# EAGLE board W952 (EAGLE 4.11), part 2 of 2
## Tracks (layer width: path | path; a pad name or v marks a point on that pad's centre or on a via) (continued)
N$696 (continued)
  Bottom 0.508: SV62.12 136.53,74.3 140.34,70.49 IC31.24 IC39.24
N$699
  Bottom 0.508: SV63.2 95.25,48.9 99.06,52.71 IC32.1 IC40.1
N$700
  Bottom 0.508: SV63.3 98.42,49.53 101.6,52.71 IC32.2 IC40.2
N$701
  Bottom 0.508: SV63.4 101.6,48.9 104.14,51.44 IC32.3 IC40.3
N$702
  Bottom 0.508: SV63.5 104.78,48.9 106.68,50.8 IC32.4 IC40.4
N$703
  Bottom 0.508: SV63.6 107.95,48.9 109.22,50.17 IC32.5 IC40.5
N$704
  Bottom 0.508: SV63.7 111.76,48.26 IC32.6 IC40.6
N$705
  Bottom 0.508: SV63.8 IC32.7 IC40.7
N$706
  Bottom 0.508: SV63.9 116.84,48.26 IC32.8 IC40.8
N$707
  Bottom 0.508: SV63.10 120.65,48.9 119.38,50.17 IC32.9 IC40.9
N$708
  Bottom 0.508: SV63.11 123.83,48.9 121.92,50.8 IC32.10 IC40.10
N$709
  Bottom 0.508: SV63.12 127,48.9 124.46,51.44 IC32.11 IC40.11
N$710
  Bottom 0.508: SV63.13 130.18,49.53 127,52.71 IC32.12 IC40.12
N$711
  Bottom 0.508: SV64.1 130.18,74.93 127,71.76 IC32.13 IC40.13
N$712
  Bottom 0.508: SV64.2 127,74.93 124.46,72.39 IC32.14 IC40.14
N$713
  Bottom 0.508: SV64.3 123.83,74.93 121.92,73.03 IC32.15 IC40.15
N$714
  Bottom 0.508: SV64.4 120.65,74.93 119.38,73.66 IC32.16 IC40.16
N$715
  Bottom 0.508: SV64.5 116.84,75.57 IC32.17 IC40.17
N$716
  Bottom 0.508: SV64.6 IC32.18 IC40.18
N$717
  Bottom 0.508: SV64.7 111.76,75.57 IC32.19 IC40.19
N$718
  Bottom 0.508: SV64.8 107.95,74.93 109.22,73.66 IC32.20 IC40.20
N$719
  Bottom 0.508: SV64.9 104.78,74.93 106.68,73.03 IC32.21 IC40.21
N$720
  Bottom 0.508: SV64.10 101.6,74.93 104.14,72.39 IC32.22 IC40.22
N$721
  Bottom 0.508: SV64.11 98.42,74.93 101.6,71.76 IC32.23 IC40.23
N$722
  Bottom 0.508: SV64.12 95.25,74.3 99.06,70.49 IC32.24 IC40.24
N$725
  Bottom 0.508: SV65.2 136.53,87 140.34,90.81 IC33.1 IC41.1
N$726
  Bottom 0.508: SV65.3 139.7,87.63 142.88,90.81 IC33.2 IC41.2
N$727
  Bottom 0.508: SV65.4 142.88,87 145.41,89.54 IC33.3 IC41.3
N$728
  Bottom 0.508: SV65.5 146.05,87 147.96,88.9 IC33.4 IC41.4
N$729
  Bottom 0.508: SV65.6 149.22,87 150.5,88.27 IC33.5 IC41.5
N$730
  Bottom 0.508: SV65.7 153.03,86.36 IC33.6 IC41.6
N$731
  Bottom 0.508: SV65.8 IC33.7 IC41.7
N$732
  Bottom 0.508: SV65.9 158.12,86.36 IC33.8 IC41.8
N$733
  Bottom 0.508: SV65.10 161.93,87 160.66,88.27 IC33.9 IC41.9
N$734
  Bottom 0.508: SV65.11 165.1,87 163.19,88.9 IC33.10 IC41.10
N$735
  Bottom 0.508: SV65.12 168.28,87 165.74,89.54 IC33.11 IC41.11
N$736
  Bottom 0.508: SV65.13 171.45,87.63 168.28,90.81 IC33.12 IC41.12
N$737
  Bottom 0.508: SV66.1 171.45,113.03 168.28,109.86 IC33.13 IC41.13
N$738
  Bottom 0.508: SV66.2 168.28,113.03 165.74,110.49 IC33.14 IC41.14
N$739
  Bottom 0.508: SV66.3 165.1,113.03 163.19,111.13 IC33.15 IC41.15
N$740
  Bottom 0.508: SV66.4 161.93,113.03 160.66,111.76 IC33.16 IC41.16
N$741
  Bottom 0.508: SV66.5 158.12,113.67 IC33.17 IC41.17
N$742
  Bottom 0.508: SV66.6 IC33.18 IC41.18
N$743
  Bottom 0.508: SV66.7 153.03,113.67 IC33.19 IC41.19
N$744
  Bottom 0.508: SV66.8 149.22,113.03 150.5,111.76 IC33.20 IC41.20
N$745
  Bottom 0.508: SV66.9 146.05,113.03 147.96,111.13 IC33.21 IC41.21
N$746
  Bottom 0.508: SV66.10 142.88,113.03 145.41,110.49 IC33.22 IC41.22
N$747
  Bottom 0.508: SV66.11 139.7,113.03 142.88,109.86 IC33.23 IC41.23
N$748
  Bottom 0.508: SV66.12 136.53,112.4 140.34,108.59 IC33.24 IC41.24
N$751
  Bottom 0.508: SV67.2 95.25,87 99.06,90.81 IC34.1 IC42.1
N$752
  Bottom 0.508: SV67.3 98.42,87.63 101.6,90.81 IC34.2 IC42.2
N$753
  Bottom 0.508: SV67.4 101.6,87 104.14,89.54 IC34.3 IC42.3
N$754
  Bottom 0.508: SV67.5 104.78,87 106.68,88.9 IC34.4 IC42.4
N$755
  Bottom 0.508: SV67.6 107.95,87 109.22,88.27 IC34.5 IC42.5
N$756
  Bottom 0.508: SV67.7 111.76,86.36 IC34.6 IC42.6
N$757
  Bottom 0.508: SV67.8 IC34.7 IC42.7
N$758
  Bottom 0.508: SV67.9 116.84,86.36 IC34.8 IC42.8
N$759
  Bottom 0.508: SV67.10 120.65,87 119.38,88.27 IC34.9 IC42.9
N$760
  Bottom 0.508: SV67.11 123.83,87 121.92,88.9 IC34.10 IC42.10
N$761
  Bottom 0.508: SV67.12 127,87 124.46,89.54 IC34.11 IC42.11
N$762
  Bottom 0.508: SV67.13 130.18,87.63 127,90.81 IC34.12 IC42.12
N$763
  Bottom 0.508: SV68.1 130.18,113.03 127,109.86 IC34.13 IC42.13
N$764
  Bottom 0.508: SV68.2 127,113.03 124.46,110.49 IC34.14 IC42.14
N$765
  Bottom 0.508: SV68.3 123.83,113.03 121.92,111.13 IC34.15 IC42.15
N$766
  Bottom 0.508: SV68.4 120.65,113.03 119.38,111.76 IC34.16 IC42.16
N$767
  Bottom 0.508: SV68.5 116.84,113.67 IC34.17 IC42.17
N$768
  Bottom 0.508: SV68.6 IC34.18 IC42.18
N$769
  Bottom 0.508: SV68.7 111.76,113.67 IC34.19 IC42.19
N$770
  Bottom 0.508: SV68.8 107.95,113.03 109.22,111.76 IC34.20 IC42.20
N$771
  Bottom 0.508: SV68.9 104.78,113.03 106.68,111.13 IC34.21 IC42.21
N$772
  Bottom 0.508: SV68.10 101.6,113.03 104.14,110.49 IC34.22 IC42.22
N$773
  Bottom 0.508: SV68.11 98.42,113.03 101.6,109.86 IC34.23 IC42.23
N$774
  Bottom 0.508: SV68.12 95.25,112.4 99.06,108.59 IC34.24 IC42.24
N$777
  Bottom 0.508: SV69.2 136.53,125.1 140.34,128.91 IC35.1 IC43.1
N$778
  Bottom 0.508: SV69.3 139.7,125.73 142.88,128.91 IC35.2 IC43.2
N$779
  Bottom 0.508: SV69.4 142.88,125.1 145.41,127.64 IC35.3 IC43.3
N$780
  Bottom 0.508: SV69.5 146.05,125.1 147.96,127 IC35.4 IC43.4
N$781
  Bottom 0.508: SV69.6 149.22,125.1 150.5,126.37 IC35.5 IC43.5
N$782
  Bottom 0.508: SV69.7 153.03,124.46 IC35.6 IC43.6
N$783
  Bottom 0.508: SV69.8 IC35.7 IC43.7
N$784
  Bottom 0.508: SV69.9 158.12,124.46 IC35.8 IC43.8
N$785
  Bottom 0.508: SV69.10 161.93,125.1 160.66,126.37 IC35.9 IC43.9
N$786
  Bottom 0.508: SV69.11 165.1,125.1 163.19,127 IC35.10 IC43.10
N$787
  Bottom 0.508: SV69.12 168.28,125.1 165.74,127.64 IC35.11 IC43.11
N$788
  Bottom 0.508: SV69.13 171.45,125.73 168.28,128.91 IC35.12 IC43.12
N$789
  Bottom 0.508: SV70.1 171.45,151.13 168.28,147.96 IC35.13 IC43.13
N$790
  Bottom 0.508: SV70.2 168.28,151.13 165.74,148.59 IC35.14 IC43.14
N$791
  Bottom 0.508: SV70.3 165.1,151.13 163.19,149.23 IC35.15 IC43.15
N$792
  Bottom 0.508: SV70.4 161.93,151.13 160.66,149.86 IC35.16 IC43.16
N$793
  Bottom 0.508: SV70.5 158.12,151.77 IC35.17 IC43.17
N$794
  Bottom 0.508: SV70.6 IC35.18 IC43.18
N$795
  Bottom 0.508: SV70.7 153.03,151.77 IC35.19 IC43.19
N$796
  Bottom 0.508: SV70.8 149.22,151.13 150.5,149.86 IC35.20 IC43.20
N$797
  Bottom 0.508: SV70.9 146.05,151.13 147.96,149.23 IC35.21 IC43.21
N$798
  Bottom 0.508: SV70.10 142.88,151.13 145.41,148.59 IC35.22 IC43.22
N$799
  Bottom 0.508: SV70.11 139.7,151.13 142.88,147.96 IC35.23 IC43.23
N$800
  Bottom 0.508: SV70.12 136.53,150.5 140.34,146.69 IC35.24 IC43.24
N$803
  Bottom 0.508: SV71.2 95.25,125.1 99.06,128.91 IC36.1 IC44.1
N$804
  Bottom 0.508: SV71.3 98.42,125.73 101.6,128.91 IC36.2 IC44.2
N$805
  Bottom 0.508: SV71.4 101.6,125.1 104.14,127.64 IC36.3 IC44.3
N$806
  Bottom 0.508: SV71.5 104.78,125.1 106.68,127 IC36.4 IC44.4
N$807
  Bottom 0.508: SV71.6 107.95,125.1 109.22,126.37 IC36.5 IC44.5
N$808
  Bottom 0.508: SV71.7 111.76,124.46 IC36.6 IC44.6
N$809
  Bottom 0.508: SV71.8 IC36.7 IC44.7
N$810
  Bottom 0.508: SV71.9 116.84,124.46 IC36.8 IC44.8
N$811
  Bottom 0.508: SV71.10 120.65,125.1 119.38,126.37 IC36.9 IC44.9
N$812
  Bottom 0.508: SV71.11 123.83,125.1 121.92,127 IC36.10 IC44.10
N$813
  Bottom 0.508: SV71.12 127,125.1 124.46,127.64 IC36.11 IC44.11
N$814
  Bottom 0.508: SV71.13 130.18,125.73 127,128.91 IC36.12 IC44.12
N$815
  Bottom 0.508: SV72.1 130.18,151.13 127,147.96 IC36.13 IC44.13
N$816
  Bottom 0.508: SV72.2 127,151.13 124.46,148.59 IC36.14 IC44.14
N$817
  Bottom 0.508: SV72.3 123.83,151.13 121.92,149.23 IC36.15 IC44.15
N$818
  Bottom 0.508: SV72.4 120.65,151.13 119.38,149.86 IC36.16 IC44.16
N$819
  Bottom 0.508: SV72.5 116.84,151.77 IC36.17 IC44.17
N$820
  Bottom 0.508: SV72.6 IC36.18 IC44.18
N$821
  Bottom 0.508: SV72.7 111.76,151.77 IC36.19 IC44.19
N$822
  Bottom 0.508: SV72.8 107.95,151.13 109.22,149.86 IC36.20 IC44.20
N$823
  Bottom 0.508: SV72.9 104.78,151.13 106.68,149.23 IC36.21 IC44.21
N$824
  Bottom 0.508: SV72.10 101.6,151.13 104.14,148.59 IC36.22 IC44.22
N$825
  Bottom 0.508: SV72.11 98.42,151.13 101.6,147.96 IC36.23 IC44.23
N$826
  Bottom 0.508: SV72.12 95.25,150.5 99.06,146.69 IC36.24 IC44.24
N$829
  Bottom 0.508: SV73.2 136.53,163.2 140.34,167.01 IC37.1 IC45.1
N$830
  Bottom 0.508: SV73.3 139.7,163.83 142.88,167.01 IC37.2 IC45.2
N$831
  Bottom 0.508: SV73.4 142.88,163.2 145.41,165.74 IC37.3 IC45.3
N$832
  Bottom 0.508: SV73.5 146.05,163.2 147.96,165.1 IC37.4 IC45.4
N$833
  Bottom 0.508: SV73.6 149.22,163.2 150.5,164.47 IC37.5 IC45.5
N$834
  Bottom 0.508: SV73.7 153.03,162.56 IC37.6 IC45.6
N$835
  Bottom 0.508: SV73.8 IC37.7 IC45.7
N$836
  Bottom 0.508: SV73.9 158.12,162.56 IC37.8 IC45.8
N$837
  Bottom 0.508: SV73.10 161.93,163.2 160.66,164.47 IC37.9 IC45.9
N$838
  Bottom 0.508: SV73.11 165.1,163.2 163.19,165.1 IC37.10 IC45.10
N$839
  Bottom 0.508: SV73.12 168.28,163.2 165.74,165.74 IC37.11 IC45.11
N$840
  Bottom 0.508: SV73.13 171.45,163.83 168.28,167.01 IC37.12 IC45.12
N$841
  Bottom 0.508: SV74.1 171.45,189.23 168.28,186.06 IC37.13 IC45.13
N$842
  Bottom 0.508: SV74.2 168.28,189.23 165.74,186.69 IC37.14 IC45.14
N$843
  Bottom 0.508: SV74.3 165.1,189.23 163.19,187.33 IC37.15 IC45.15
N$844
  Bottom 0.508: SV74.4 161.93,189.23 160.66,187.96 IC37.16 IC45.16
N$845
  Bottom 0.508: SV74.5 158.12,189.87 IC37.17 IC45.17
N$846
  Bottom 0.508: SV74.6 IC37.18 IC45.18
N$847
  Bottom 0.508: SV74.7 153.03,189.87 IC37.19 IC45.19
N$848
  Bottom 0.508: SV74.8 149.22,189.23 150.5,187.96 IC37.20 IC45.20
N$849
  Bottom 0.508: SV74.9 146.05,189.23 147.96,187.33 IC37.21 IC45.21
N$850
  Bottom 0.508: SV74.10 142.88,189.23 145.41,186.69 IC37.22 IC45.22
N$851
  Bottom 0.508: SV74.11 139.7,189.23 142.88,186.06 IC37.23 IC45.23
N$852
  Bottom 0.508: SV74.12 136.53,188.6 140.34,184.79 IC37.24 IC45.24
N$855
  Bottom 0.508: SV75.2 95.25,163.2 99.06,167.01 IC38.1 IC46.1
N$856
  Bottom 0.508: SV75.3 98.42,163.83 101.6,167.01 IC38.2 IC46.2
N$857
  Bottom 0.508: SV75.4 101.6,163.2 104.14,165.74 IC38.3 IC46.3
N$858
  Bottom 0.508: SV75.5 104.78,163.2 106.68,165.1 IC38.4 IC46.4
N$859
  Bottom 0.508: SV75.6 107.95,163.2 109.22,164.47 IC38.5 IC46.5
N$860
  Bottom 0.508: SV75.7 111.76,162.56 IC38.6 IC46.6
N$861
  Bottom 0.508: SV75.8 IC38.7 IC46.7
N$862
  Bottom 0.508: SV75.9 116.84,162.56 IC38.8 IC46.8
N$863
  Bottom 0.508: SV75.10 120.65,163.2 119.38,164.47 IC38.9 IC46.9
N$864
  Bottom 0.508: SV75.11 123.83,163.2 121.92,165.1 IC38.10 IC46.10
N$865
  Bottom 0.508: SV75.12 127,163.2 124.46,165.74 IC38.11 IC46.11
N$866
  Bottom 0.508: SV75.13 130.18,163.83 127,167.01 IC38.12 IC46.12
N$867
  Bottom 0.508: SV76.1 130.18,189.23 127,186.06 IC38.13 IC46.13
N$868
  Bottom 0.508: SV76.2 127,189.23 124.46,186.69 IC38.14 IC46.14
N$869
  Bottom 0.508: SV76.3 123.83,189.23 121.92,187.33 IC38.15 IC46.15
N$870
  Bottom 0.508: SV76.4 120.65,189.23 119.38,187.96 IC38.16 IC46.16
N$871
  Bottom 0.508: SV76.5 116.84,189.87 IC38.17 IC46.17
N$872
  Bottom 0.508: SV76.6 IC38.18 IC46.18
N$873
  Bottom 0.508: SV76.7 111.76,189.87 IC38.19 IC46.19
N$874
  Bottom 0.508: SV76.8 107.95,189.23 109.22,187.96 IC38.20 IC46.20
N$875
  Bottom 0.508: SV76.9 104.78,189.23 106.68,187.33 IC38.21 IC46.21
N$876
  Bottom 0.508: SV76.10 101.6,189.23 104.14,186.69 IC38.22 IC46.22
N$877
  Bottom 0.508: SV76.11 98.42,189.23 101.6,186.06 IC38.23 IC46.23
N$878
  Bottom 0.508: SV76.12 95.25,188.6 99.06,184.79 IC38.24 IC46.24
VCC
  Bottom 0.762: SV54.9 C27.1 16.51,76.2 | C22.1 SV44.9 33.66,76.2 31.75,74.3 21.59,74.3 19.68,76.2 16.51,76.2 | SV56.9 C28.1 16.51,107.95 | C23.1 SV46.9 33.66,107.95 31.75,106.05 21.59,106.05 19.68,107.95 16.51,107.95 | 16.51,107.95 16.51,76.2 | C16.1 SV32.9 64.14,43.82 64.14,36.83 C40.+ 59.05,30.48 | 59.05,30.48 U$5.A1 57.15,31.75 44.45,44.45 C21.1 SV42.9 33.66,44.45 31.75,42.55 21.59,42.55 19.68,44.45 16.51,44.45 | SV52.9 C26.1 16.51,44.45 | 59.05,30.48 59.05,20.96 58.42,20.32 58.42,13.97 U$1.DA2 | 16.51,76.2 16.51,44.45 | C33.1 SV66.13 130.81,116.84 94.61,116.84 SV68.13 92.08,106.05 | 92.08,106.05 C34.1 | 73.66,107.95 76.83,107.95 78.74,106.05 92.08,106.05 | 73.66,107.95 C18.1 SV36.9 59.69,111.76 59.69,139.07 | SV62.13 C31.1 | SV34.9 C17.1 73.66,76.2 | 92.08,74.3 C32.1 | 92.08,74.3 SV64.13 94.61,78.74 130.81,78.74 SV62.13 | 73.66,76.2 76.83,76.2 78.74,74.3 92.08,74.3 | 73.66,76.2 73.66,107.95 | C37.1 SV74.13 130.81,193.04 94.61,193.04 SV76.13 C38.1 92.08,175.26 90.17,173.36 90.17,168.91 | C35.1 SV70.13 130.81,154.94 90.81,154.94 | C36.1 SV72.13 92.08,153.67 90.81,154.94 | 90.17,168.91 90.17,155.58 90.81,154.94 | C19.1 SV38.9 60.33,139.7 59.69,139.07 | SV58.9 C29.1 16.51,139.7 | 16.51,139.7 19.68,139.7 21.59,137.8 31.75,137.8 33.66,139.7 SV48.9 C24.1 43.18,139.7 45.09,137.8 58.42,137.8 59.69,139.07 | SV60.9 C30.1 16.51,171.45 | 16.51,171.45 19.68,171.45 21.59,169.55 31.75,169.55 33.66,171.45 SV50.9 C25.1 43.18,171.45 45.09,169.55 58.42,169.55 60.33,171.45 SV40.9 64.14,170.82 C20.1 71.75,170.82 73.66,168.91 90.17,168.91 | 16.51,139.7 16.51,171.45 | 16.51,139.7 16.51,107.95 | U$1.CA2 128.27,13.97 128.27,16.51 128.91,17.15 128.91,23.5 127,25.4 U$4.A1 127.64,29.21 130.81,29.21 146.05,44.45 SV22.9 C11.1 185.42,43.82 195.58,33.66
  Bottom 0.762: SV12.9 C6.1 | 195.58,33.66 192.41,30.48 | 192.41,30.48 U$3.A1 | 195.58,33.66 C39.+ SV12.9 | 192.41,30.48 192.41,20.96 191.77,20.32 191.77,13.97 U$1.BA2 | C4.1 SV8.9 231.78,139.7 229.87,137.8 216.53,137.8 214.63,139.7 C9.1 SV18.9 205.1,139.7 203.2,137.8 193.04,137.8 191.13,139.7 187.96,139.7 | SV28.9 C14.1 187.96,139.7 | C5.1 SV10.9 231.78,171.45 229.87,169.55 216.53,169.55 214.63,171.45 C10.1 SV20.9 205.1,171.45 203.2,169.55 193.04,169.55 191.13,171.45 187.96,171.45 | SV30.9 C15.1 187.96,171.45 | 187.96,139.7 187.96,171.45 | U$1.AA2 261.62,13.97 261.62,20.32 262.25,20.96 262.25,25.4 260.35,27.31 U$2.A1 260.35,31.75 247.65,44.45 C1.1 SV2.9 231.14,48.26 231.14,75.57 | C2.1 SV4.9 231.78,76.2 231.14,75.57 | 187.96,76.2 191.13,76.2 193.04,74.3 203.2,74.3 | 203.2,74.3 205.1,76.2 SV14.9 C7.1 214.63,76.2 216.53,74.3 229.87,74.3 231.14,75.57 | 187.96,76.2 C12.1 SV24.9 176.53,76.2 173.99,78.74 135.89,78.74 SV62.13 | C3.1 SV6.9 231.78,107.95 229.87,106.05 216.53,106.05 214.63,107.95 C8.1 SV16.9 205.1,107.95 203.2,106.05 193.04,106.05 191.13,107.95 187.96,107.95 | SV26.9 C13.1 187.96,107.95 | 187.96,76.2 187.96,107.95 | 187.96,107.95 187.96,139.7 | 203.2,74.3 203.2,47.63 SV12.9

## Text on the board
Top: M952 Wire Wrappable Module | VRS
Bottom: M952 Wire Wrappable Module | VRS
